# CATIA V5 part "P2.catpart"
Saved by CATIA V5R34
Part number: Part1
Bounding box of the stored display mesh (mm): x -70 to 70, y -50 to 50, z -8 to 34
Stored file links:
  D:\Artur\Systemy CAM\2025-2026\Zaoczne\P2\P2.catpart
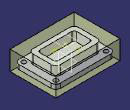
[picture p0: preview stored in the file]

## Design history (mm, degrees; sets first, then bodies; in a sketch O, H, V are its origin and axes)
WSupportSet1
Set1 "Rough stock.1"
  Sketch1 on {plane stored without definition}, origin (0, 0, -8), H (1, 0, 0), V (0, 1, 0)
    line L1 (-70, -50) -> (70, -50)
    line L2 (70, -50) -> (70, 50)
    line L3 (70, 50) -> (-70, 50)
    line L4 (-70, 50) -> (-70, -50)
  Join1: Elements ({fill Boundary Sketch1}; {fill Boundary {translate ToTransfor Sketch1, Distance 42}}; {loft Sections (Sketch1; {translate ToTransfor Sketch1, Distance 42})})
  Sketch2 on face of Join1, origin (0, 0, 34), H (1, 0, 0), V (0, 1, 0)
    point P1 (0, 0)
    coincidence: P1 O
Body1 (main body)
  Sketch3 on xy-plane, origin (0, 0, 0), H (1, 0, 0), V (0, 1, 0)
    line L1 (65, 45) -> (65, -45)
    line L2 (65, -45) -> (-65, -45)
    line L3 (-65, -45) -> (-65, 45)
    line L4 (-65, 45) -> (65, 45)
    line L5 (50, 30) -> (50, -30)
    line L6 (50, -30) -> (-50, -30)
    line L7 (-50, -30) -> (-50, 30)
    line L8 (-50, 30) -> (50, 30)
    line L9 (40, 20) -> (40, -20)
    line L10 (40, -20) -> (-40, -20)
    line L11 (-40, -20) -> (-40, 20)
    line L12 (-40, 20) -> (40, 20)
    distance L2 L4 = 90
    distance L1 L3 = 130
    distance L8 L6 = 60
    distance L5 L7 = 100
    distance L12 L10 = 40
    distance L9 L11 = 80
    vertical: L1 V, L3 V, L5 V, L7 V, L9 V, L11 V
    horizontal: L2 H, L4 H, L6 H, L8 H, L10 H, L12 H
    equidistance: L1 L3 O, L2 L4 O, L5 L7 O, L6 L8 O, L9 L11 O, L10 L12 O
  MultiPad1: profile Sketch3, domains (length 10; length 30; length 10)
  Fillet1: radius 10, on edge [face of MultiPad1 from Sketch3.L1 | face of MultiPad1 from Sketch3.L2]; edge [face of MultiPad1 from Sketch3.L5 | face of MultiPad1 from Sketch3.L6]; edge [face of MultiPad1 from Sketch3.L4 | face of MultiPad1 from Sketch3.L1]; edge [face of MultiPad1 from Sketch3.L8 | face of MultiPad1 from Sketch3.L5]; edge [face of MultiPad1 from Sketch3.L2 | face of MultiPad1 from Sketch3.L3]; edge [face of MultiPad1 from Sketch3.L6 | face of MultiPad1 from Sketch3.L7]; edge [face of MultiPad1 from Sketch3.L7 | face of MultiPad1 from Sketch3.L8]; edge [face of MultiPad1 from Sketch3.L3 | face of MultiPad1 from Sketch3.L4]
  Fillet2: radius 5, on edge [face of MultiPad1 from Sketch3.L11 | face of MultiPad1 from Sketch3.L10]; edge [face of MultiPad1 from Sketch3.L9 | face of MultiPad1 from Sketch3.L12]; edge [face of MultiPad1 from Sketch3.L10 | face of MultiPad1 from Sketch3.L9]; edge [face of MultiPad1 from Sketch3.L12 | face of MultiPad1 from Sketch3.L11]
  Sketch4 on face of MultiPad1, origin (-42.0822, 38.8603, 10), H (1, 0, 0), V (0, 1, 0)
    point P1 (-12.9178, -3.8603)
    reference intersected line E1 through (42.0822, 0) direction (0, 1) from yz-plane
    reference intersected line E2 through (0, -38.8603) direction (-1, 0) from zx-plane
    distance P1 E1 = 55
    distance E2 P1 = 35
  Hole1: placed by Sketch4, at (-55, 35, 10) direction (0, 0, -1), diameter 10, through (limit type 6)
  RectPattern1: of Hole1, direction 1 instances 2, spacing 110, along edge [face of MultiPad1 from Sketch3.L4 | face of MultiPad1] reversed, direction 2 instances 2, spacing 70, along edge [face of MultiPad1 from Sketch3.L3 | face of MultiPad1]
  Plane1: type Offset, RefPlane face of MultiPad1, Offset 10, reversed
